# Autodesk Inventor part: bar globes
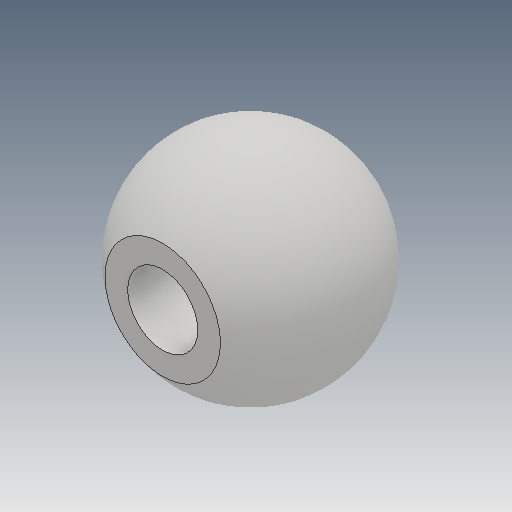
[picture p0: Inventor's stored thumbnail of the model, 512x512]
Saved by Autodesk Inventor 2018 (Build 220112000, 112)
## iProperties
Created: 2016-03
Part Number: bar globes
Material: Generic
Document SubType Name: Modeling
Designer: Sandeep
Density: 1 g/cm^3
Appearance: Default
Mass: 0.753654 g
Surface Area: 5.66286 cm^2
Volume: 0.753654 cm^3
Author: Sandeep
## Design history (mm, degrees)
sketch "Sketch1"
  geometry: L1 (0, 12)-(0, 0); A1 r 6 centre (0, 6) between (0, 12) and (0, 0)
  constraints: 2 end point, 2 point on circle, 1 centre point, 1 midpoint, 1 vertical
revolve "Revolution1" sketch "Sketch1" stored, may be unused: angle "d1" = 90 deg
sketch "Sketch2"
  geometry: 1 further point
sketch "Sketch3"
  geometry: 1 further point
sketch "Sketch4"
  geometry: 1 further point
sketch "Sketch5"
  geometry: L1 (5.014, 9.295)-(5.014, 2.705); A1 r 6 centre (0, 6) between (0, 0) and (5.014, 9.295) reference; A2 r 6 centre (0, 6) between (0, 0) and (5.014, 2.705) reference; 2 further points
  constraints: 2 end point, 2 point on circle, 1 vertical, 1 vertical alignment
extrude "Extrusion1" cut sketch "Sketch5" stored distance "d2" = 10; taper "d3" = 0 deg
sketch "Sketch6"
  geometry: L1 (5.65, 4.164)-(5.65, -4.091); A1 r 6 centre (0, 0) between (-5.014, -3.295) and (-5.014, 3.295) reference; 1 further point
  constraints: 2 end point, 1 vertical
extrude "Extrusion2" cut sketch "Sketch6" distance "d5" = 15.75; taper "d6" = 0 deg
sketch "Sketch7"
  geometry: L1 (-5.65, 3.981)-(-5.65, 8.019) reference; L2 (-5.65, 6)-(5.014, 6); L3 (-4.986, 8)-(5.014, 8); L4 (5.014, 8)-(5.014, 6); L5 (5.014, 9.295)-(5.014, 2.705) reference; L6 (-5.65, 7.336)-(-5.65, 6); L7 (-4.986, 8)-(-5.65, 7.336); 3 further points
  constraints: 10 end point, 2 collinear, 2 horizontal, 2 midpoint, 2 point on line
  dimensions: "d16" = 4 diameter of L3 L2; "d17" = 10 distance of L3.end L3.start; "d19" = 45 deg angle of L7 L3
revolve "Revolution2" sketch "Sketch7" stored, may be unused: angle "d18" = 90 deg
body "Solid1"
other parameters: "d4" = 15.75
